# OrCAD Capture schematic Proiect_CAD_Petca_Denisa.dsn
size A
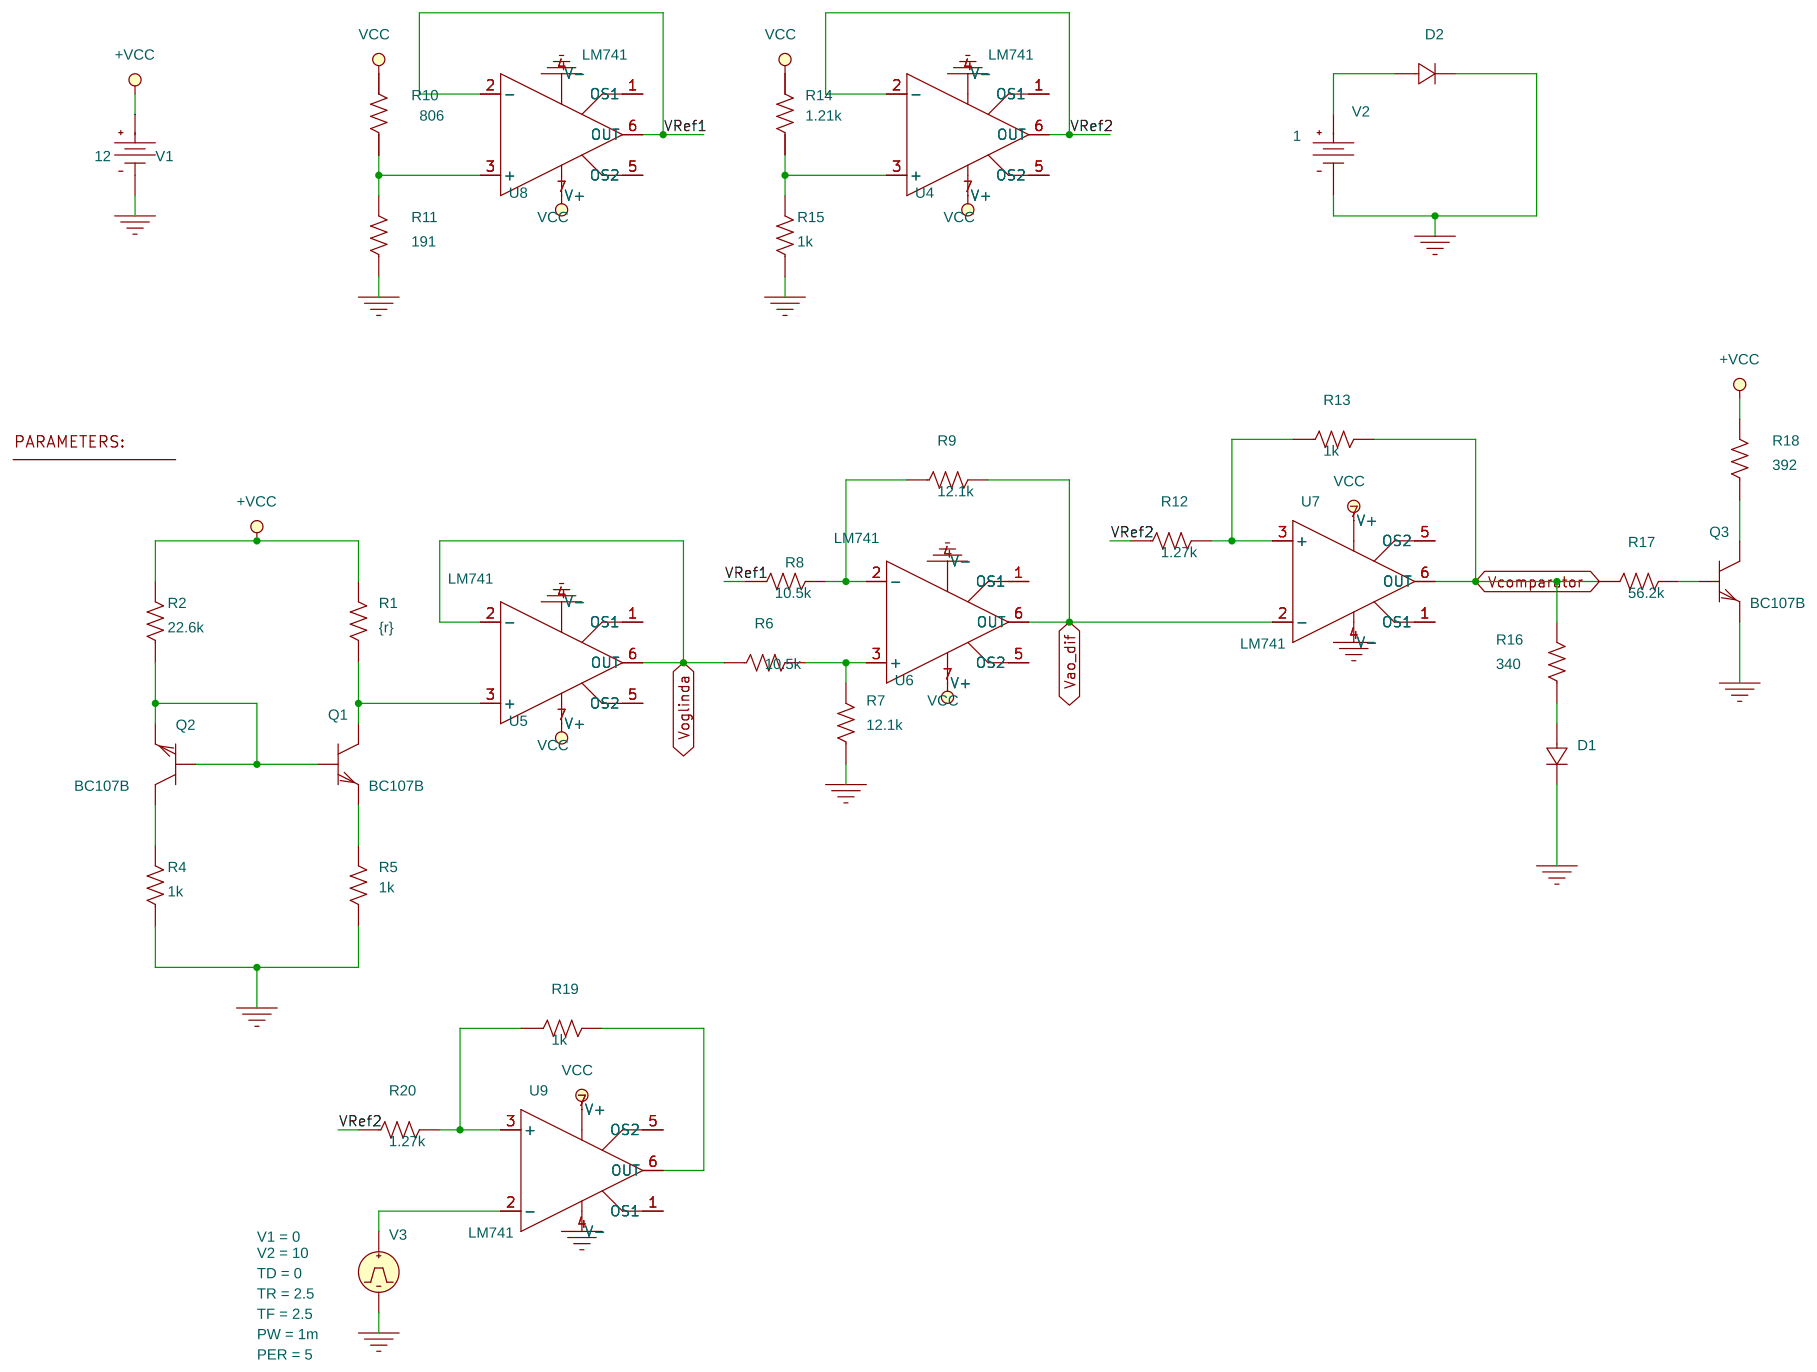
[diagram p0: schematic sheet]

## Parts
1  PARAM
D1  Dbreak
D2  Dbreak
Q1  BC107B  [TO18]
Q2  BC107B  [TO18]
Q3  BC107B  [TO18]
R1  {r}  [AXRC05]
R2  22.6k  [AXRC05]
R4  1k  [AXRC05]
R5  1k  [AXRC05]
R6  10.5k  [AXRC05]
R7  12.1k  [AXRC05]
R8  10.5k  [AXRC05]
R9  12.1k  [AXRC05]
R10  806  [AXRC05]
R11  191  [AXRC05]
R12  1.27k  [AXRC05]
R13  1k  [AXRC05]
R14  1.21k  [AXRC05]
R15  1k  [AXRC05]
R16  340  [AXRC05]
R17  56.2k  [AXRC05]
R18  392  [AXRC05]
R19  1k  [AXRC05]
R20  1.27k  [AXRC05]
U4  LM741  [DIP1008W300L450]
U5  LM741  [DIP1008W300L450]
U6  LM741  [DIP1008W300L450]
U7  LM741  [DIP1008W300L450]
U8  LM741  [DIP1008W300L450]
U9  LM741  [DIP1008W300L450]
V1  VDC
V2  VDC
V3  VPULSE

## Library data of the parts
1 = PARAM: r: 20k
D1 D2 = Dbreak: PSpiceTemplate: D^@REFDES  %1 %2 @MODEL ?AREA/@AREA/
Q1-Q3 = BC107B
R1 R2 R4-R20 = R: TOLERANCE: 1%
U4-U9 = LM741
V1 = VDC: DC: 12
V2 = VDC: DC: 1
V3 = VPULSE: PER: 5; PW: 1m; TD: 0; TF: 2.5; TR: 2.5; V1: 0; V2: 10

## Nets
+VCC: R1.2 R2.2 R10.2 R14.2 R18.2 U4.7(V+) U5.7(V+) U6.7(V+) U7.7(V+) U8.7(V+) U9.7(V+) V1.0(+)
0: D1.1(2) D2.1(2) Q3.1(e) R4.1 R5.1 R7.1 R11.1 R15.1 U4.4(V-) U5.4(V-) U6.4(V-) U7.4(V-) U8.4(V-) U9.4(V-) V1.1(-) V2.1(-) V3.2(-)
Vao_dif: R9.2 U6.6(OUT) U7.2(-)
Vcomparator: R13.2 R16.2 R17.1 U7.6(OUT)
Voglinda: R6.1 U5.2(-) U5.6(OUT)
VRef1: R8.1 U8.2(-) U8.6(OUT)
VRef2: R12.1 R20.1 U4.2(-) U4.6(OUT)
N40169: R10.1 R11.2 U8.3(+)
N40173: R14.1 R15.2 U4.3(+)
N40347: R12.2 R13.1 U7.3(+)
N40409: R8.2 R9.1 U6.2(-)
N40437: Q3.3(c) R18.1
N40727: Q3.2(b) R17.2
N40891: Q1.2(b) Q2.1(e) Q2.2(b) R2.1
N40895: Q1.3(c) R1.1 U5.3(+)
N40917: R6.2 R7.2 U6.3(+)
N40993: D1.0(1) R16.1
N41103: Q2.3(c) R4.2
N41109: Q1.1(e) R5.2
N51564: D2.0(1) V2.0(+)
N59137: R19.1 R20.2 U9.3(+)
N59147: R19.2 U9.6(OUT)
N59257: U9.2(-) V3.1(+)

Not connected (* = marked no-connect by the designer): U4 1(OS1) 5(OS2); U5 1(OS1) 5(OS2); U6 1(OS1) 5(OS2); U7 1(OS1) 5(OS2); U8 1(OS1) 5(OS2); U9 1(OS1) 5(OS2)
